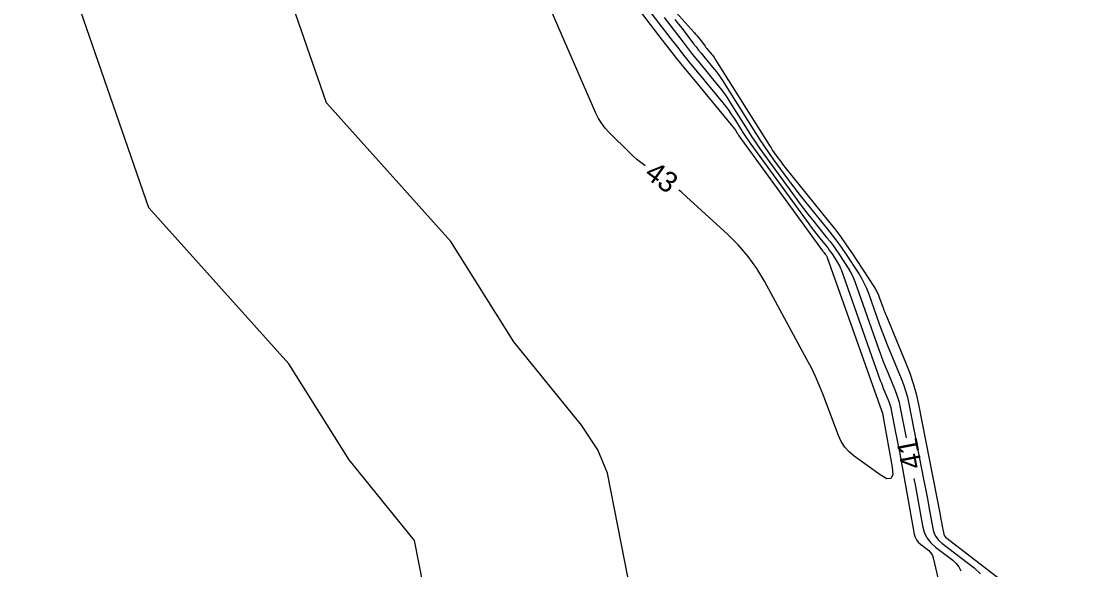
# Model space of a CAD drawing. Extents: x 2384780 to 2405861, y 547869 to 573706.
# Drawn here: x 2390263.6 to 2390367.8, y 552209.3 to 552262.4 of the extents above; entities that cross this region are included whole.
import ezdxf

# ---------------------------------------------------------------- set-up
doc = ezdxf.new("R2010")
doc.units = 0
for name, color, linetype in [('Old_Level_60', 7, 'Continuous'), ('Old_Level_61', 7, 'Continuous'), ('Prop Buffer Zone 1', 7, 'Continuous'), ('Prop Buffer Zone 2', 7, 'Continuous')]:
    doc.layers.add(name, color=color, linetype=linetype)

msp = doc.modelspace()

# ---------------------------------------------------------------- linework, layer by layer
at = {"layer": 'Old_Level_60'}
for points in [[(2390324.16175, 552248.4285), (2390324.10025, 552248.47125), (2390323.70625, 552248.7575), (2390323.32575, 552249.05975), (2390322.9585, 552249.378), (2390322.6045, 552249.7125), (2390320.6515, 552251.63925), (2390320.256, 552252.068), (2390319.9065, 552252.52825), (2390319.60275, 552253.02), (2390319.34525, 552253.54325), (2390311.97075, 552270.48425)], [(2390321.61, 552269.4505), (2390328.87475, 552261.354), (2390329.01475, 552261.19475), (2390329.15175, 552261.03275), (2390329.28575, 552260.86825), (2390329.41625, 552260.701), (2390329.83775, 552260.15025), (2390329.9285, 552260.03275), (2390330.0205, 552259.916), (2390330.11375, 552259.8005), (2390330.208, 552259.6855), (2390330.59025, 552259.225), (2390330.67025, 552259.125), (2390330.747, 552259.0225), (2390330.8205, 552258.91775), (2390330.8905, 552258.81025), (2390336.1805, 552250.39675), (2390336.3295, 552250.16425), (2390336.482, 552249.9345), (2390336.6385, 552249.70725), (2390336.799, 552249.4825), (2390337.329, 552248.75275), (2390337.4435, 552248.59725), (2390337.56025, 552248.44325), (2390337.679, 552248.29075), (2390337.79975, 552248.14), (2390341.8765, 552243.11275), (2390342.47725, 552242.353), (2390343.0585, 552241.579), (2390343.6205, 552240.79075), (2390344.163, 552239.9885), (2390346.307, 552236.7315), (2390346.46975, 552236.46725), (2390346.61575, 552236.1945), (2390346.745, 552235.9135), (2390346.8575, 552235.624), (2390347.19725, 552234.665), (2390347.2715, 552234.46), (2390347.34825, 552234.25625), (2390347.428, 552234.05325), (2390347.51025, 552233.8515), (2390349.399, 552229.31025), (2390349.7785, 552228.3295), (2390350.10775, 552227.33325), (2390350.3865, 552226.322), (2390350.61475, 552225.2955), (2390352.71075, 552214.623), (2390352.757, 552214.38425), (2390352.80275, 552214.14525), (2390352.84725, 552213.90625), (2390352.89125, 552213.667), (2390353.033, 552212.8855), (2390353.0765, 552212.726), (2390353.146, 552212.58225), (2390353.242, 552212.45475), (2390353.36375, 552212.343), (2390359.30225, 552207.783)], [(2390320.74775, 552267.18975), (2390325.546, 552260.9195), (2390326.352, 552259.877), (2390327.16825, 552258.8425), (2390327.9945, 552257.816), (2390328.831, 552256.79775), (2390332.623, 552252.2265), (2390332.689, 552252.14425), (2390332.752, 552252.06025), (2390332.81225, 552251.974), (2390332.86975, 552251.88575), (2390333.053, 552251.5945), (2390333.09275, 552251.53225), (2390333.1335, 552251.471), (2390333.1755, 552251.41025), (2390333.21825, 552251.35025), (2390341.315, 552240.20475), (2390341.348, 552240.16), (2390341.3815, 552240.11575), (2390341.4155, 552240.072), (2390341.45025, 552240.0285), (2390341.5645, 552239.8875), (2390341.5885, 552239.857), (2390341.612, 552239.826), (2390341.6345, 552239.7945), (2390341.65625, 552239.76225), (2390341.731, 552239.64875), (2390341.74625, 552239.624), (2390341.75975, 552239.5985), (2390341.772, 552239.57225), (2390341.7825, 552239.54525), (2390347.03125, 552224.7305), (2390347.041, 552224.70325), (2390347.05125, 552224.67625), (2390347.06175, 552224.64925), (2390347.07275, 552224.6225), (2390347.109, 552224.535), (2390347.1165, 552224.51625), (2390347.12275, 552224.497), (2390347.128, 552224.4775), (2390347.1325, 552224.45775), (2390347.174, 552224.24625), (2390347.18275, 552224.201), (2390347.1915, 552224.1555), (2390347.2, 552224.11025), (2390347.20825, 552224.06475), (2390348.08525, 552219.232), (2390348.13725, 552218.48875), (2390347.956, 552218.11625), (2390347.54175, 552218.11425), (2390346.89425, 552218.483), (2390344.39875, 552220.2925), (2390343.90175, 552220.709), (2390343.48, 552221.183), (2390343.13375, 552221.71475), (2390342.86275, 552222.304), (2390341.343, 552226.329), (2390341.003, 552227.18475), (2390340.634, 552228.0275), (2390340.23625, 552228.85675), (2390339.8095, 552229.673), (2390335.68175, 552237.24625), (2390334.9365, 552238.4905), (2390334.09675, 552239.6605), (2390333.16275, 552240.757), (2390332.13425, 552241.7795), (2390328.142, 552245.43725), (2390327.62075, 552245.89875), (2390327.39925, 552246.082)], [(2390323.2545, 552265.1235), (2390326.61175, 552260.737), (2390327.2425, 552259.92075), (2390327.8815, 552259.111), (2390328.52825, 552258.3075), (2390329.183, 552257.51025), (2390331.64125, 552254.547), (2390331.9425, 552254.1715), (2390332.231, 552253.7865), (2390332.507, 552253.39225), (2390332.76975, 552252.98875), (2390333.608, 552251.65575), (2390333.79, 552251.37175), (2390333.9765, 552251.09075), (2390334.168, 552250.813), (2390334.364, 552250.5385), (2390339.9875, 552242.79725), (2390340.20775, 552242.49825), (2390340.432, 552242.20225), (2390340.66025, 552241.909), (2390340.89225, 552241.619), (2390341.65675, 552240.67625), (2390341.818, 552240.47225), (2390341.974, 552240.2645), (2390342.12475, 552240.053), (2390342.2705, 552239.83775), (2390342.77025, 552239.07825), (2390342.87225, 552238.913), (2390342.9635, 552238.7425), (2390343.0445, 552238.56675), (2390343.11475, 552238.3855), (2390346.92225, 552227.639), (2390347.02475, 552227.3555), (2390347.13125, 552227.07325), (2390347.24125, 552226.79275), (2390347.35525, 552226.5135), (2390347.7335, 552225.604), (2390347.8095, 552225.4075), (2390347.8755, 552225.208), (2390347.93125, 552225.0055), (2390347.977, 552224.8), (2390348.4095, 552222.59725), (2390348.5015, 552222.125), (2390348.5915, 552221.6525), (2390348.68, 552221.17975), (2390348.76675, 552220.7065), (2390350.2125, 552212.739), (2390350.29125, 552212.44975), (2390350.4175, 552212.1895), (2390350.59125, 552211.958), (2390350.81225, 552211.7555), (2390351.612, 552211.1415), (2390351.768, 552211.00025), (2390351.8935, 552210.839), (2390351.98825, 552210.65825), (2390352.05275, 552210.4575), (2390356.11325, 552193.03275)], [(2390325.94875, 552262.81275), (2390327.79275, 552260.403), (2390328.1905, 552259.88875), (2390328.593, 552259.37825), (2390329.00075, 552258.872), (2390329.4135, 552258.3695), (2390331.053, 552256.393), (2390331.397, 552255.964), (2390331.7265, 552255.52475), (2390332.0415, 552255.07475), (2390332.3415, 552254.614), (2390334.0645, 552251.87375), (2390334.4385, 552251.28975), (2390334.82225, 552250.7125), (2390335.2155, 552250.1415), (2390335.61825, 552249.577), (2390338.66, 552245.39), (2390339.06775, 552244.8365), (2390339.48275, 552244.2885), (2390339.905, 552243.74625), (2390340.33425, 552243.2095), (2390341.749, 552241.465), (2390342.0475, 552241.0875), (2390342.336, 552240.70325), (2390342.61525, 552240.31175), (2390342.88475, 552239.91325), (2390343.80975, 552238.508), (2390343.99825, 552238.202), (2390344.16725, 552237.88625), (2390344.31675, 552237.561), (2390344.447, 552237.226), (2390346.81325, 552230.54725), (2390347.0085, 552230.0075), (2390347.211, 552229.4705), (2390347.42075, 552228.93625), (2390347.63775, 552228.40475), (2390348.358, 552226.673), (2390348.50275, 552226.299), (2390348.62825, 552225.919), (2390348.7345, 552225.5335), (2390348.8215, 552225.142), (2390349.424, 552222.07425)], [(2390350.179, 552218.146), (2390350.32525, 552217.34825), (2390351.01625, 552213.5395), (2390351.18075, 552212.9355), (2390351.4445, 552212.392), (2390351.807, 552211.909), (2390352.26875, 552211.48625), (2390353.9385, 552210.204), (2390354.2645, 552209.9085), (2390354.5265, 552209.57225), (2390354.7245, 552209.1945)]]:
    msp.add_lwpolyline(points, dxfattribs=at)
at = {"layer": 'Old_Level_61'}
msp.add_lwpolyline([(2390326.99925, 552262.6135), (2390327.3545, 552262.17625), (2390327.7015, 552261.732), (2390328.821, 552260.26925), (2390329.06225, 552259.957), (2390329.30675, 552259.64725), (2390329.55425, 552259.33975), (2390329.80475, 552259.03475), (2390330.81975, 552257.811), (2390331.03275, 552257.5455), (2390331.23675, 552257.2735), (2390331.43175, 552256.995), (2390331.6175, 552256.70975), (2390334.858, 552251.556), (2390335.2535, 552250.9385), (2390335.659, 552250.328), (2390336.07475, 552249.7245), (2390336.50075, 552249.12775), (2390337.90875, 552247.1895), (2390338.21325, 552246.77625), (2390338.523, 552246.367), (2390338.83825, 552245.96225), (2390339.159, 552245.56125), (2390341.798, 552242.307), (2390342.25475, 552241.72925), (2390342.69675, 552241.14075), (2390343.12425, 552240.54125), (2390343.53675, 552239.93125), (2390344.8605, 552237.92025), (2390345.13025, 552237.4825), (2390345.37225, 552237.03075), (2390345.58625, 552236.56525), (2390345.7725, 552236.086), (2390346.8205, 552233.1275), (2390347.0495, 552232.495), (2390347.2865, 552231.866), (2390347.53225, 552231.24025), (2390347.78625, 552230.6175), (2390348.94225, 552227.83825), (2390349.1745, 552227.23825), (2390349.37575, 552226.62875), (2390349.5465, 552226.00975), (2390349.68625, 552225.3815), (2390351.15225, 552217.91575), (2390351.2755, 552217.28175), (2390351.39675, 552216.64725), (2390351.5155, 552216.01225), (2390351.632, 552215.377), (2390352.00875, 552213.30075), (2390352.124, 552212.877), (2390352.309, 552212.4955), (2390352.5635, 552212.1565), (2390352.88725, 552211.86), (2390356.01375, 552209.45925), (2390356.624, 552208.90625)], dxfattribs=at)
at = {"layer": 'Prop Buffer Zone 1'}
msp.add_lwpolyline([(2390381.91392, 552100.88942), (2390373.74029, 552114.41903), (2390369.492, 552120.65244), (2390359.01808, 552134.8571), (2390357.68104, 552145.6376), (2390348.41018, 552160.60663), (2390347.16241, 552177.82329), (2390342.24599, 552181.79693), (2390325.11994, 552194.94772), (2390320.46539, 552218.64918), (2390319.52705, 552220.90534), (2390317.94684, 552223.30582), (2390311.39735, 552231.38212), (2390305.28942, 552241.09657), (2390293.23735, 552254.52821), (2390284.57271, 552279.52131), (2390282.67512, 552290.97372)], dxfattribs=at)
at = {"layer": 'Prop Buffer Zone 2'}
msp.add_lwpolyline([(2390365.13392, 552090.75214), (2390357.238, 552103.82207), (2390353.49719, 552109.31086), (2390340.19426, 552127.35221), (2390338.75404, 552138.96467), (2390329.20548, 552154.38208), (2390328.22996, 552167.84215), (2390307.30933, 552183.90673), (2390301.76597, 552212.13413), (2390295.4282, 552219.94935), (2390289.58218, 552229.24725), (2390276.00817, 552244.37505), (2390263.64927, 552280.0242)], dxfattribs=at)

# ---------------------------------------------------------------- texts
at = {"layer": 'Old_Level_60'}
for s, rotation, p in [('43', 324.0666194, (2390323.9365, 552247.40675)), ('41', 100.8787694, (2390350.992, 552219.24875))]:
    msp.add_text(s, height=2, rotation=rotation, dxfattribs=at).set_placement(p)

doc.saveas('drawing.dxf')
